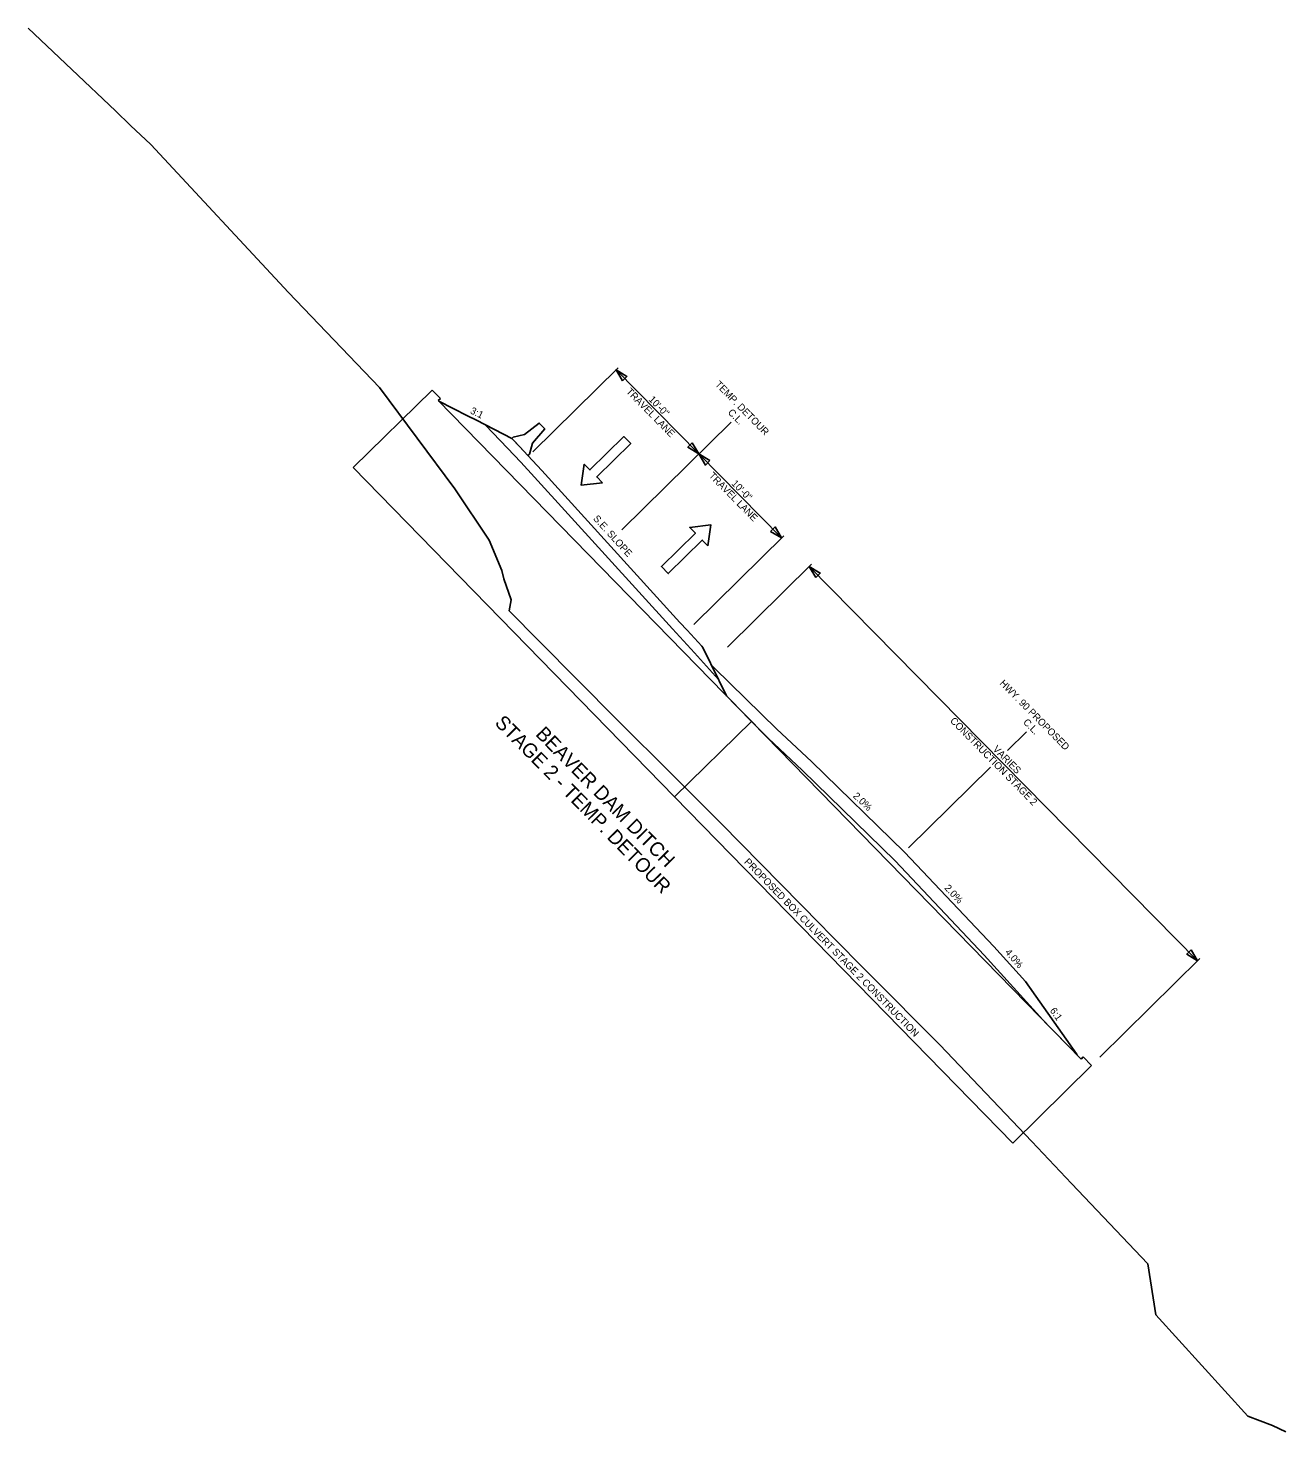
# Model space of a CAD drawing. Extents: x 1660188 to 1660468, y 670370 to 670621.
# Drawn here: x 1660188.3 to 1660294.9, y 670502.4 to 670621.3 of the extents above; entities that cross this region are included whole.
import ezdxf

# ---------------------------------------------------------------- set-up
doc = ezdxf.new("R2010")
doc.units = 0
for name, color, linetype in [('Default', 7, 'Continuous'), ('R_Annotation', 7, 'Continuous'), ('R_Concrete', 7, 'Continuous'), ('R_Dimension', 7, 'Continuous'), ('R_Exist Surface', 7, 'Continuous'), ('R_Fin Surface', 7, 'Continuous'), ('R_Horz Alg', 7, 'Continuous'), ('R_MOT', 7, 'Continuous')]:
    doc.layers.add(name, color=color, linetype=linetype)

msp = doc.modelspace()

# ---------------------------------------------------------------- linework, layer by layer
at = {"layer": 'Default'}
for points in [[(1660237, 670582.78), (1660235.21, 670582.56), (1660235.46, 670584.35), (1660235.94, 670583.86), (1660238.82, 670586.69), (1660239.4, 670586.11), (1660236.52, 670583.27)], [(1660245.94, 670577.43), (1660246.19, 670579.21), (1660244.4, 670579), (1660244.88, 670578.51), (1660242, 670575.67), (1660242.58, 670575.08), (1660245.46, 670577.92)]]:
    msp.add_lwpolyline(points, close=True, dxfattribs=at)
at = {"layer": 'R_Concrete'}
for p, q in [((1660249.64, 670562.55), (1660243.11, 670556.17)), ((1660277.56, 670533.95), (1660249.64, 670562.55)), ((1660243.11, 670556.17), (1660271.76, 670526.83)), ((1660271.76, 670526.83), (1660278.44, 670533.41)), ((1660277.56, 670533.95), (1660277.73, 670534.13)), ((1660277.73, 670534.13), (1660278.44, 670533.41))]:
    msp.add_line(p, q, dxfattribs=at)
at = {"layer": 'R_Dimension'}
for p, q in [((1660231.1, 670585.41), (1660238.34, 670592.53)), ((1660238.15, 670592.35), (1660245.16, 670585.22)), ((1660252.18, 670578.1), (1660245.16, 670585.22)), ((1660244.74, 670570.77), (1660252.37, 670578.28)), ((1660247.6, 670568.86), (1660254.72, 670575.87)), ((1660254.53, 670575.69), (1660287.43, 670542.27)), ((1660279.15, 670534.11), (1660287.62, 670542.46))]:
    msp.add_line(p, q, dxfattribs=at)
for points in [[(1660238.7, 670591.41), (1660238.15, 670592.35), (1660239.08, 670591.78)], [(1660244.61, 670586.16), (1660245.16, 670585.22), (1660244.24, 670585.79)], [(1660246.09, 670584.65), (1660245.16, 670585.22), (1660245.72, 670584.28)], [(1660251.25, 670578.66), (1660252.18, 670578.1), (1660251.63, 670579.03)], [(1660255.08, 670574.75), (1660254.53, 670575.69), (1660255.46, 670575.12)], [(1660286.88, 670543.21), (1660287.43, 670542.27), (1660286.51, 670542.84)]]:
    msp.add_lwpolyline(points, close=True, dxfattribs=at)
at = {"layer": 'R_Exist Surface'}
msp.add_lwpolyline([(1660188.34, 670621.3), (1660195.73, 670614.3), (1660197.02, 670613.05), (1660198.75, 670611.43), (1660210.41, 670598.91), (1660218.12, 670590.86), (1660224.5, 670582.25), (1660227.4, 670577.9), (1660228.49, 670575.34), (1660228.64, 670574.64), (1660229.26, 670572.87), (1660229.1, 670571.92), (1660231.64, 670569.36), (1660238.23, 670562.71), (1660243, 670557.96), (1660247.05, 670553.9), (1660255.49, 670545.34), (1660256.24, 670544.55), (1660259.59, 670541.17), (1660265.6, 670535.15), (1660273.39, 670526.96), (1660276.75, 670523.4), (1660283.22, 670516.59), (1660283.88, 670512.28), (1660291.69, 670503.68), (1660293.77, 670502.89), (1660294.91, 670502.35)], dxfattribs=at)
at = {"layer": 'R_Fin Surface'}
for p, q in [((1660246.24, 670567.32), (1660247.52, 670564.72)), ((1660247.52, 670564.72), (1660250.78, 670561.38)), ((1660274.61, 670536.97), (1660277.21, 670534.31))]:
    msp.add_line(p, q, dxfattribs=at)
for points in [[(1660246.24, 670567.32), (1660246.49, 670567.08), (1660251.79, 670561.91), (1660254.71, 670559.17), (1660262.58, 670551.49), (1660270.15, 670543.49), (1660272.84, 670540.53), (1660277.16, 670534.39), (1660277.21, 670534.31)], [(1660250.78, 670561.38), (1660251.04, 670561.13), (1660253.96, 670558.39), (1660261.81, 670550.73), (1660269.35, 670542.76), (1660274.61, 670536.97)]]:
    msp.add_lwpolyline(points, dxfattribs=at)
at = {"layer": 'R_Horz Alg'}
for p, q in [((1660238.63, 670578.79), (1660247.91, 670587.92)), ((1660271.31, 670560.08), (1660272.93, 670561.68)), ((1660262.94, 670551.84), (1660269.88, 670558.67))]:
    msp.add_line(p, q, dxfattribs=at)
at = {"layer": 'R_MOT'}
for p, q in [((1660222.58, 670590.63), (1660215.87, 670584.08)), ((1660222.58, 670590.63), (1660223.27, 670589.91)), ((1660223.27, 670589.91), (1660223.09, 670589.74)), ((1660223.09, 670589.74), (1660249.64, 670562.55)), ((1660215.87, 670584.08), (1660243.11, 670556.17))]:
    msp.add_line(p, q, dxfattribs=at)
for points in [[(1660223.14, 670589.69), (1660225.58, 670588.45), (1660226.33, 670588.07), (1660229.32, 670586.54), (1660229.57, 670586.28), (1660230.69, 670585.09), (1660231.86, 670583.81), (1660237.43, 670577.69), (1660243.56, 670570.95), (1660244.17, 670570.29), (1660245.41, 670568.92), (1660245.51, 670568.81), (1660246.83, 670566.11)], [(1660227.1, 670587.67), (1660228.96, 670585.7), (1660230.08, 670584.52), (1660231.24, 670583.25), (1660242.95, 670570.39), (1660243.55, 670569.73), (1660244.79, 670568.36), (1660246.83, 670566.11)], [(1660230.69, 670585.09), (1660230, 670585.82), (1660229.32, 670586.54), (1660229.44, 670586.65), (1660230.39, 670586.87), (1660231.65, 670587.83), (1660232.11, 670587.35), (1660231.07, 670586.14), (1660230.81, 670585.21), (1660230.69, 670585.09)]]:
    msp.add_lwpolyline(points, dxfattribs=at)

# ---------------------------------------------------------------- texts
at = {"layer": 'R_Annotation'}
for s, height, rotation, p in [('TRAVEL LANE', 0.6, 314.5576, (1660238.96, 670590.46)), ('TEMP. DETOUR', 0.6, 314.5576, (1660246.5, 670591.06)), ('10\'-0"', 0.6, 314.5576, (1660240.87, 670589.79)), ('3:1', 0.6, 333.3952, (1660225.74, 670588.69)), ('C.L.', 0.6, 314.5576, (1660247.58, 670588.69)), ('TRAVEL LANE', 0.6, 314.5576, (1660245.97, 670583.33)), ('10\'-0"', 0.6, 314.5576, (1660247.89, 670582.67)), ('S.E. SLOPE', 0.6, 312.322, (1660236.17, 670579.71)), ('HWY. 90 PROPOSED', 0.6, 314.5576, (1660270.61, 670565.74)), ('STAGE 2 - TEMP. DETOUR', 1.2, 314.5226, (1660227.81, 670562.36)), ('BEAVER DAM DITCH', 1.2, 314.5226, (1660231.27, 670561.41)), ('CONSTRUCTION STAGE 2', 0.6, 314.5576, (1660266.41, 670562.56)), ('C.L.', 0.6, 314.5576, (1660272.6, 670562.44)), ('VARIES', 0.6, 314.5576, (1660270.04, 670560.16)), ('2.0%', 0.6, 316.5576, (1660258.18, 670556.18)), ('PROPOSED BOX CULVERT STAGE 2 CONSTRUCTION', 0.6, 314.3141, (1660248.97, 670550.61)), ('2.0%', 0.6, 312.5576, (1660265.93, 670548.41)), ('4.0%', 0.6, 310.5576, (1660271.07, 670542.97)), ('6:1', 0.6, 305.0953, (1660274.88, 670538.05))]:
    msp.add_text(s, height=height, rotation=rotation, dxfattribs=at).set_placement(p)

doc.saveas('drawing.dxf')
